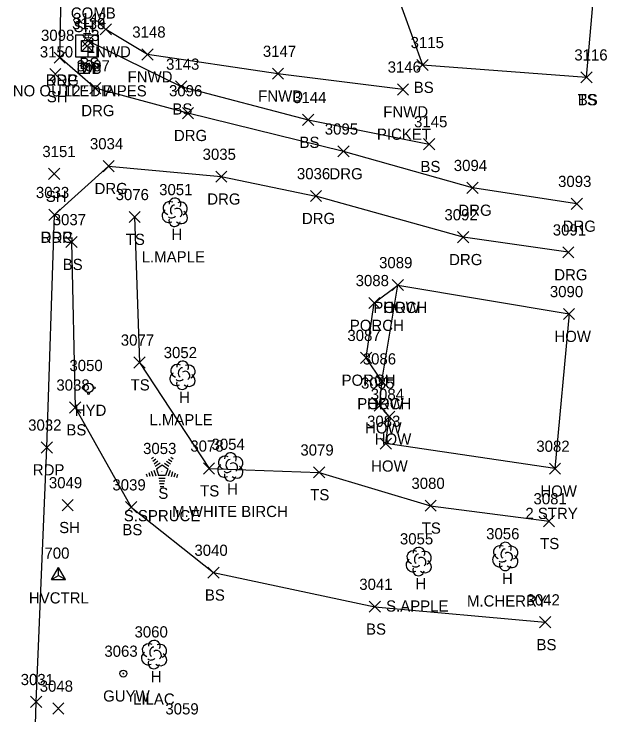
# Model space of a CAD drawing. Extents: x 1609623 to 1616187, y 756677 to 762826.
# Drawn here: x 1610619.9 to 1610725.9, y 762230.4 to 762355.6 of the extents above; entities that cross this region are included whole.
import ezdxf

# ---------------------------------------------------------------- set-up
doc = ezdxf.new("R2010")
doc.units = 0
for name, color, linetype in [('C_A', 7, 'Continuous'), ('C_I', 7, 'Continuous'), ('CPSM', 7, 'Continuous'), ('D_A', 7, 'Continuous'), ('D_C', 7, 'Continuous'), ('D_I', 7, 'Continuous'), ('D_TIC', 7, 'Continuous'), ('DS', 7, 'Continuous'), ('L_A', 7, 'Continuous'), ('L_C', 7, 'Continuous'), ('L_I', 7, 'Continuous'), ('L_TIC', 7, 'Continuous'), ('LBC', 7, 'Continuous'), ('LBF', 7, 'Continuous'), ('LELB', 7, 'Continuous'), ('LFNC', 7, 'Continuous'), ('LTC', 7, 'Continuous'), ('LTD', 7, 'Continuous'), ('P_A', 7, 'Continuous'), ('P_I', 7, 'Continuous'), ('P_TIC', 7, 'Continuous'), ('PET', 7, 'Continuous'), ('R_A', 7, 'Continuous'), ('R_I', 7, 'Continuous'), ('R_TIC', 7, 'Continuous'), ('RDG', 7, 'Continuous'), ('U_A', 7, 'Continuous'), ('U_C', 7, 'Continuous'), ('U_I', 7, 'Continuous'), ('UPGW', 7, 'Continuous'), ('UWFH', 7, 'Continuous')]:
    doc.layers.add(name, color=color, linetype=linetype)

msp = doc.modelspace()

# ---------------------------------------------------------------- linework, layer by layer
at = {"layer": 'CPSM'}
for p, q in [((1610626.64, 762254.57), (1610627.89, 762256.74)), ((1610629.14, 762254.57), (1610627.89, 762256.74)), ((1610627.89, 762255.3), (1610627.89, 762256.74)), ((1610626.64, 762254.57), (1610627.89, 762255.3)), ((1610627.89, 762255.3), (1610627.89, 762255.3)), ((1610627.89, 762255.3), (1610629.14, 762254.57)), ((1610626.64, 762254.57), (1610629.14, 762254.57))]:
    msp.add_line(p, q, dxfattribs=at)
at = {"layer": 'D_TIC'}
for points in [[(1610631.99, 762348.87), (1610633.99, 762350.87)], [(1610633.99, 762348.87), (1610631.99, 762350.87)]]:
    msp.add_lwpolyline(points, dxfattribs=at)
at = {"layer": 'DS'}
for p, q in [((1610630.97, 762351.87), (1610634.97, 762351.87)), ((1610630.97, 762347.87), (1610630.97, 762351.87)), ((1610634.97, 762351.87), (1610634.97, 762347.87)), ((1610631.97, 762348.87), (1610631.97, 762350.87)), ((1610631.97, 762350.87), (1610633.97, 762350.87)), ((1610633.97, 762350.87), (1610633.97, 762348.87)), ((1610632.98, 762349.87), (1610632.98, 762349.87)), ((1610632.98, 762349.87), (1610632.98, 762349.87)), ((1610634.97, 762347.87), (1610630.97, 762347.87)), ((1610633.97, 762348.87), (1610631.97, 762348.87))]:
    msp.add_line(p, q, dxfattribs=at)
at = {"layer": 'L_TIC'}
for points in [[(1610635.31, 762351.84), (1610637.31, 762353.84)], [(1610637.31, 762351.84), (1610635.31, 762353.84)], [(1610632.16, 762349.79), (1610634.16, 762351.79)], [(1610634.16, 762349.79), (1610632.16, 762351.79)], [(1610642.75, 762347.37), (1610644.75, 762349.37)], [(1610644.75, 762347.37), (1610642.75, 762349.37)], [(1610691.89, 762345.49), (1610693.89, 762347.49)], [(1610693.89, 762345.49), (1610691.89, 762347.49)], [(1610626.31, 762343.83), (1610628.31, 762345.83)], [(1610628.31, 762343.83), (1610626.31, 762345.83)], [(1610666.07, 762343.93), (1610668.07, 762345.93)], [(1610668.07, 762343.93), (1610666.07, 762345.93)], [(1610721.2, 762343.28), (1610723.2, 762345.28)], [(1610723.2, 762343.28), (1610721.2, 762345.28)], [(1610721.2, 762343.28), (1610723.2, 762345.28)], [(1610723.2, 762343.28), (1610721.2, 762345.28)], [(1610648.78, 762341.63), (1610650.78, 762343.63)], [(1610650.78, 762341.63), (1610648.78, 762343.63)], [(1610688.42, 762341.12), (1610690.42, 762343.12)], [(1610690.42, 762341.12), (1610688.42, 762343.12)], [(1610671.47, 762335.67), (1610673.47, 762337.67)], [(1610673.47, 762335.67), (1610671.47, 762337.67)], [(1610693.09, 762331.35), (1610695.09, 762333.35)], [(1610695.09, 762331.35), (1610693.09, 762333.35)], [(1610626.1, 762326.03), (1610628.1, 762328.03)], [(1610628.1, 762326.03), (1610626.1, 762328.03)], [(1610640.47, 762318.34), (1610642.47, 762320.34)], [(1610642.47, 762318.34), (1610640.47, 762320.34)], [(1610629.18, 762313.86), (1610631.18, 762315.86)], [(1610631.18, 762313.86), (1610629.18, 762315.86)], [(1610687.49, 762306.18), (1610689.49, 762308.18)], [(1610689.49, 762306.18), (1610687.49, 762308.18)], [(1610687.49, 762306.18), (1610689.49, 762308.18)], [(1610689.49, 762306.18), (1610687.49, 762308.18)], [(1610683.29, 762302.98), (1610685.29, 762304.98)], [(1610685.29, 762302.98), (1610683.29, 762304.98)], [(1610718.07, 762301.01), (1610720.07, 762303.01)], [(1610720.07, 762301.01), (1610718.07, 762303.01)], [(1610681.82, 762293.18), (1610683.82, 762295.18)], [(1610683.82, 762293.18), (1610681.82, 762295.18)], [(1610641.34, 762292.35), (1610643.34, 762294.35)], [(1610643.34, 762292.35), (1610641.34, 762294.35)], [(1610684.62, 762288.99), (1610686.62, 762290.99)], [(1610686.62, 762288.99), (1610684.62, 762290.99)], [(1610684.62, 762288.99), (1610686.62, 762290.99)], [(1610686.62, 762288.99), (1610684.62, 762290.99)], [(1610684.25, 762284.67), (1610686.25, 762286.67)], [(1610686.25, 762284.67), (1610684.25, 762286.67)], [(1610629.83, 762284.32), (1610631.83, 762286.32)], [(1610631.83, 762284.32), (1610629.83, 762286.32)], [(1610685.97, 762282.67), (1610687.97, 762284.67)], [(1610687.97, 762282.67), (1610685.97, 762284.67)], [(1610685.34, 762277.85), (1610687.34, 762279.85)], [(1610687.34, 762277.85), (1610685.34, 762279.85)], [(1610653.76, 762273.42), (1610655.76, 762275.42)], [(1610655.76, 762273.42), (1610653.76, 762275.42)], [(1610715.56, 762273.39), (1610717.56, 762275.39)], [(1610717.56, 762273.39), (1610715.56, 762275.39)], [(1610673.42, 762272.72), (1610675.42, 762274.72)], [(1610675.42, 762272.72), (1610673.42, 762274.72)], [(1610628.5, 762266.87), (1610630.5, 762268.87)], [(1610630.5, 762266.87), (1610628.5, 762268.87)], [(1610639.84, 762266.49), (1610641.84, 762268.49)], [(1610641.84, 762266.49), (1610639.84, 762268.49)], [(1610693.35, 762266.77), (1610695.35, 762268.77)], [(1610695.35, 762266.77), (1610693.35, 762268.77)], [(1610714.5, 762264.01), (1610716.5, 762266.01)], [(1610716.5, 762264.01), (1610714.5, 762266.01)], [(1610654.57, 762254.81), (1610656.57, 762256.81)], [(1610656.57, 762254.81), (1610654.57, 762256.81)], [(1610683.37, 762248.73), (1610685.37, 762250.73)], [(1610685.37, 762248.73), (1610683.37, 762250.73)], [(1610713.81, 762245.95), (1610715.81, 762247.95)], [(1610715.81, 762245.95), (1610713.81, 762247.95)], [(1610626.84, 762230.54), (1610628.84, 762232.54)], [(1610628.84, 762230.54), (1610626.84, 762232.54)]]:
    msp.add_lwpolyline(points, dxfattribs=at)
at = {"layer": 'LBC'}
for points in [[(1610716.56, 762274.39), (1610686.34, 762278.85), (1610686.97, 762283.67), (1610685.25, 762285.67), (1610685.62, 762289.99), (1610688.49, 762307.18), (1610719.07, 762302.01)], [(1610719.07, 762302.01), (1610716.56, 762274.39)]]:
    msp.add_lwpolyline(points, dxfattribs=at)
at = {"layer": 'LBF'}
msp.add_lwpolyline([(1610685.62, 762289.99), (1610682.82, 762294.18), (1610684.29, 762303.98), (1610688.49, 762307.18)], dxfattribs=at)
at = {"layer": 'LELB'}
for points in [[(1610697.13, 762426.27), (1610674.89, 762430.11), (1610652.17, 762434), (1610639.18, 762426.74), (1610634.28, 762401.02), (1610634.83, 762377.24), (1610647.78, 762368.68), (1610668.95, 762368.97), (1610685.96, 762365.63), (1610692.89, 762346.49), (1610722.2, 762344.28)], [(1610722.2, 762344.28), (1610724.11, 762366.05), (1610703.11, 762368.06), (1610688.81, 762373.62), (1610671.14, 762377.72), (1610655.71, 762382.19), (1610654.46, 762391.1), (1610655.72, 762413.08), (1610653.02, 762429.54), (1610669.88, 762427.1), (1610693.44, 762424.02)], [(1610633.16, 762350.79), (1610649.78, 762342.63), (1610672.47, 762336.67), (1610694.09, 762332.35)], [(1610641.47, 762319.34), (1610642.34, 762293.35), (1610654.76, 762274.42), (1610674.42, 762273.72), (1610694.35, 762267.77), (1610715.5, 762265.01)], [(1610630.18, 762314.86), (1610630.83, 762285.32), (1610640.84, 762267.49), (1610655.57, 762255.81), (1610684.37, 762249.73), (1610714.81, 762246.95)]]:
    msp.add_lwpolyline(points, dxfattribs=at)
at = {"layer": 'LFNC'}
msp.add_lwpolyline([(1610689.42, 762342.12), (1610667.07, 762344.93), (1610643.75, 762348.37), (1610636.31, 762352.84)], dxfattribs=at)
at = {"layer": 'LTC'}
for p, q in [((1610644.51, 762276.19), (1610644.86, 762276.45)), ((1610647.91, 762276.43), (1610648.33, 762276.13)), ((1610644.72, 762275.73), (1610645.25, 762276.11)), ((1610644.93, 762275.26), (1610645.63, 762275.77)), ((1610645.14, 762274.8), (1610646.02, 762275.43)), ((1610645.36, 762274.34), (1610646.37, 762275.08)), ((1610646.37, 762275.08), (1610647.37, 762274.35)), ((1610646.79, 762275.39), (1610647.6, 762274.8)), ((1610647.17, 762275.74), (1610647.85, 762275.24)), ((1610647.54, 762276.09), (1610648.09, 762275.69)), ((1610644.45, 762273.91), (1610644.72, 762273.07)), ((1610644.91, 762274.12), (1610645.24, 762273.1)), ((1610645.36, 762274.34), (1610645.75, 762273.15)), ((1610647.37, 762274.35), (1610646.98, 762273.15)), ((1610647.81, 762274.08), (1610647.47, 762273.04)), ((1610648.25, 762273.83), (1610647.97, 762272.95)), ((1610643.54, 762273.47), (1610643.69, 762273)), ((1610644, 762273.69), (1610644.21, 762273.04)), ((1610646.98, 762273.15), (1610645.75, 762273.15)), ((1610646.94, 762272.65), (1610645.8, 762272.65)), ((1610648.7, 762273.58), (1610648.46, 762272.85)), ((1610649.14, 762273.33), (1610648.96, 762272.76)), ((1610646.86, 762272.15), (1610645.87, 762272.15)), ((1610646.77, 762271.65), (1610645.94, 762271.65)), ((1610646.69, 762271.15), (1610646.02, 762271.15))]:
    msp.add_line(p, q, dxfattribs=at)
at = {"layer": 'LTD'}
for p, q in [((1610648.62, 762320.22), (1610648.62, 762320.22)), ((1610648.62, 762320.22), (1610648.62, 762320.22)), ((1610650, 762291.12), (1610650, 762291.12)), ((1610650, 762291.12), (1610650, 762291.12)), ((1610658.54, 762274.74), (1610658.54, 762274.74)), ((1610658.54, 762274.74), (1610658.54, 762274.74)), ((1610692.2, 762257.85), (1610692.2, 762257.85)), ((1610692.2, 762257.85), (1610692.2, 762257.85)), ((1610707.66, 762258.76), (1610707.66, 762258.76)), ((1610707.66, 762258.76), (1610707.66, 762258.76)), ((1610644.92, 762241.23), (1610644.92, 762241.23)), ((1610644.92, 762241.23), (1610644.92, 762241.23))]:
    msp.add_line(p, q, dxfattribs=at)
for centre in [(1610648.66, 762321.65), (1610650.04, 762292.55), (1610658.59, 762276.18), (1610692.25, 762259.28), (1610707.71, 762260.19), (1610644.97, 762242.67)]:
    msp.add_arc(centre, 1.05, 335.5272, 180.9563, dxfattribs=at)
for centre, major_axis, ratio, start_param, end_param in [((1610647.83, 762320.88), (1.21, -0.51), 0.895232, 1.570796, 4.712389), ((1610648.41, 762320.67), (-0.208, -0.792), 0.645439, 3.141593, 6.283185), ((1610649.66, 762320.8), (-1.14, -0.48), 0.949671, 1.570796, 4.712389), ((1610647.53, 762319.51), (0.58, -1.04), 0.959034, 3.141593, 6.283185), ((1610649.12, 762320.05), (-0.5, 0.667), 0.989748, 3.141593, 6.283185), ((1610649.62, 762319.38), (-1.09, 0.79), 0.841452, 1.570796, 4.712389), ((1610648.62, 762318.72), (0.26, 1.06), 0.942809, 1.570796, 4.712389), ((1610648.16, 762319.47), (-0.625, -0.083), 0.423636, 0, 3.141593), ((1610649.21, 762291.79), (1.21, -0.51), 0.895232, 1.570796, 4.712389), ((1610651.04, 762291.7), (-1.14, -0.48), 0.949671, 1.570796, 4.712389), ((1610648.91, 762290.41), (0.58, -1.04), 0.959034, 3.141593, 6.283185), ((1610649.79, 762291.58), (-0.208, -0.792), 0.645439, 3.141593, 6.283185), ((1610650.5, 762290.95), (-0.5, 0.667), 0.989748, 3.141593, 6.283185), ((1610649.54, 762290.37), (-0.625, -0.083), 0.423636, 0, 3.141593), ((1610651, 762290.29), (-1.09, 0.79), 0.841452, 1.570796, 4.712389), ((1610650, 762289.62), (0.26, 1.06), 0.942809, 1.570796, 4.712389), ((1610657.75, 762275.41), (1.21, -0.51), 0.895232, 1.570796, 4.712389), ((1610659.58, 762275.33), (-1.14, -0.48), 0.949671, 1.570796, 4.712389), ((1610657.46, 762274.04), (0.58, -1.04), 0.959034, 3.141593, 6.283185), ((1610658.33, 762275.2), (-0.208, -0.792), 0.645439, 3.141593, 6.283185), ((1610659.04, 762274.58), (-0.5, 0.667), 0.989748, 3.141593, 6.283185), ((1610658.08, 762273.99), (-0.625, -0.083), 0.423636, 0, 3.141593), ((1610659.54, 762273.91), (-1.09, 0.79), 0.841452, 1.570796, 4.712389), ((1610658.54, 762273.24), (0.26, 1.06), 0.942809, 1.570796, 4.712389), ((1610706.87, 762259.43), (1.21, -0.51), 0.895232, 1.570796, 4.712389), ((1610707.45, 762259.22), (-0.208, -0.792), 0.645439, 3.141593, 6.283185), ((1610708.7, 762259.34), (-1.14, -0.48), 0.949671, 1.570796, 4.712389), ((1610691.41, 762258.51), (1.21, -0.51), 0.895232, 1.570796, 4.712389), ((1610691.99, 762258.31), (-0.208, -0.792), 0.645439, 3.141593, 6.283185), ((1610693.24, 762258.43), (-1.14, -0.48), 0.949671, 1.570796, 4.712389), ((1610706.58, 762258.05), (0.58, -1.04), 0.959034, 3.141593, 6.283185), ((1610708.16, 762258.59), (-0.5, 0.667), 0.989748, 3.141593, 6.283185), ((1610708.66, 762257.93), (-1.09, 0.79), 0.841452, 1.570796, 4.712389), ((1610691.12, 762257.14), (0.58, -1.04), 0.959034, 3.141593, 6.283185), ((1610692.7, 762257.68), (-0.5, 0.667), 0.989748, 3.141593, 6.283185), ((1610693.2, 762257.01), (-1.09, 0.79), 0.841452, 1.570796, 4.712389), ((1610707.2, 762258.01), (-0.625, -0.083), 0.423636, 0, 3.141593), ((1610692.2, 762256.35), (0.26, 1.06), 0.942809, 1.570796, 4.712389), ((1610691.74, 762257.1), (-0.625, -0.083), 0.423636, 0, 3.141593), ((1610707.66, 762257.26), (0.26, 1.06), 0.942809, 1.570796, 4.712389), ((1610644.13, 762241.9), (1.21, -0.51), 0.895232, 1.570796, 4.712389), ((1610644.71, 762241.69), (-0.208, -0.792), 0.645439, 3.141593, 6.283185), ((1610645.96, 762241.82), (-1.14, -0.48), 0.949671, 1.570796, 4.712389), ((1610643.84, 762240.53), (0.58, -1.04), 0.959034, 3.141593, 6.283185), ((1610645.42, 762241.07), (-0.5, 0.667), 0.989748, 3.141593, 6.283185), ((1610645.92, 762240.4), (-1.09, 0.79), 0.841452, 1.570796, 4.712389), ((1610644.46, 762240.48), (-0.625, -0.083), 0.423636, 0, 3.141593), ((1610644.92, 762239.73), (0.26, 1.06), 0.942809, 1.570796, 4.712389)]:
    msp.add_ellipse(centre, major_axis=major_axis, ratio=ratio, start_param=start_param, end_param=end_param, dxfattribs=at)
at = {"layer": 'P_TIC'}
for points in [[(1610627.08, 762346.79), (1610629.08, 762348.79)], [(1610629.08, 762346.79), (1610627.08, 762348.79)], [(1610626.17, 762318.71), (1610628.17, 762320.71)], [(1610628.17, 762318.71), (1610626.17, 762320.71)], [(1610624.79, 762277.17), (1610626.79, 762279.17)], [(1610626.79, 762277.17), (1610624.79, 762279.17)], [(1610622.89, 762231.72), (1610624.89, 762233.72)], [(1610624.89, 762231.72), (1610622.89, 762233.72)]]:
    msp.add_lwpolyline(points, dxfattribs=at)
at = {"layer": 'PET'}
for points in [[(1610628.08, 762347.79), (1610628.95, 762388.2), (1610629.07, 762418.54), (1610628.85, 762445.72)], [(1610622.57, 762187.86), (1610623.89, 762232.72), (1610625.79, 762278.17), (1610627.17, 762319.71)]]:
    msp.add_lwpolyline(points, dxfattribs=at)
at = {"layer": 'R_TIC'}
for points in [[(1610627.08, 762346.79), (1610629.08, 762348.79)], [(1610629.08, 762346.79), (1610627.08, 762348.79)], [(1610633.44, 762341.34), (1610635.44, 762343.34)], [(1610635.44, 762341.34), (1610633.44, 762343.34)], [(1610650, 762336.89), (1610652, 762338.89)], [(1610652, 762336.89), (1610650, 762338.89)], [(1610677.78, 762330.05), (1610679.78, 762332.05)], [(1610679.78, 762330.05), (1610677.78, 762332.05)], [(1610635.82, 762327.42), (1610637.82, 762329.42)], [(1610637.82, 762327.42), (1610635.82, 762329.42)], [(1610655.95, 762325.54), (1610657.95, 762327.54)], [(1610657.95, 762325.54), (1610655.95, 762327.54)], [(1610700.82, 762323.54), (1610702.82, 762325.54)], [(1610702.82, 762323.54), (1610700.82, 762325.54)], [(1610672.86, 762322.07), (1610674.86, 762324.07)], [(1610674.86, 762322.07), (1610672.86, 762324.07)], [(1610719.46, 762320.69), (1610721.46, 762322.69)], [(1610721.46, 762320.69), (1610719.46, 762322.69)], [(1610626.17, 762318.71), (1610628.17, 762320.71)], [(1610628.17, 762318.71), (1610626.17, 762320.71)], [(1610699.16, 762314.73), (1610701.16, 762316.73)], [(1610701.16, 762314.73), (1610699.16, 762316.73)], [(1610717.94, 762312.02), (1610719.94, 762314.02)], [(1610719.94, 762312.02), (1610717.94, 762314.02)]]:
    msp.add_lwpolyline(points, dxfattribs=at)
at = {"layer": 'RDG'}
for points in [[(1610720.46, 762321.69), (1610701.82, 762324.54), (1610678.78, 762331.05), (1610651, 762337.89), (1610634.44, 762342.34), (1610628.08, 762347.79)], [(1610627.17, 762319.71), (1610636.82, 762328.42), (1610656.95, 762326.54), (1610673.86, 762323.07)], [(1610700.16, 762315.73), (1610673.86, 762323.07)], [(1610718.94, 762313.02), (1610700.16, 762315.73)]]:
    msp.add_lwpolyline(points, dxfattribs=at)
at = {"layer": 'UPGW'}
for radius in [0.625, 0.0833]:
    msp.add_circle((1610639.45, 762237.78), radius, dxfattribs=at)
at = {"layer": 'UWFH'}
msp.add_line((1610633.25, 762288.81), (1610633.25, 762288.81), dxfattribs=at)
for centre, radius in [((1610632.25, 762288.81), 0.167), ((1610633.25, 762288.81), 0.833), ((1610634.25, 762288.81), 0.167), ((1610633.25, 762287.81), 0.167)]:
    msp.add_circle(centre, radius, dxfattribs=at)

# ---------------------------------------------------------------- texts
at = {"layer": 'C_A'}
msp.add_text('HVCTRL', height=2, dxfattribs=at).set_placement((1610622.58, 762250.3))
at = {"layer": 'C_I'}
msp.add_text('700', height=2, dxfattribs=at).set_placement((1610625.36, 762258.3))
at = {"layer": 'D_A'}
for s, p in [('DIB', (1610631.09, 762344.87)), ('DI', (1610632.03, 762344.87))]:
    msp.add_text(s, height=2, dxfattribs=at).set_placement(p)
at = {"layer": 'D_C'}
for s, p in [('NO OUTLET PIPES', (1610619.7, 762340.87)), ('12" DIA', (1610628.84, 762340.87))]:
    msp.add_text(s, height=2, dxfattribs=at).set_placement(p)
at = {"layer": 'D_I'}
for s in ['3138', '3139']:
    msp.add_text(s, height=2, dxfattribs=at).set_placement((1610630.29, 762352.87))
at = {"layer": 'L_A'}
for s, p in [('SH', (1610630.57, 762352.35)), ('FNWD', (1610632.77, 762347.84)), ('BS', (1610631.61, 762345.79)), ('FNWD', (1610640.21, 762343.37)), ('BS', (1610691.33, 762341.49)), ('SH', (1610625.79, 762339.83)), ('FNWD', (1610663.54, 762339.93)), ('TS', (1610720.61, 762339.28)), ('BS', (1610720.64, 762339.28)), ('BS', (1610648.22, 762337.63)), ('FNWD', (1610685.88, 762337.12)), ('BS', (1610670.92, 762331.67)), ('BS', (1610692.53, 762327.35)), ('SH', (1610625.59, 762322.03)), ('H', (1610648.05, 762315.22)), ('TS', (1610639.88, 762314.34)), ('BS', (1610628.62, 762309.86)), ('PORCH', (1610684.11, 762302.18)), ('HOW', (1610685.88, 762302.18)), ('PORCH', (1610679.91, 762298.98)), ('HOW', (1610716.46, 762297.01)), ('TS', (1610640.75, 762288.35)), ('PORCH', (1610678.44, 762289.18)), ('H', (1610649.43, 762286.12)), ('PORCH', (1610681.24, 762284.99)), ('HOW', (1610683.01, 762284.99)), ('HOW', (1610682.63, 762280.67)), ('BS', (1610629.27, 762280.32)), ('HOW', (1610684.36, 762278.67)), ('HOW', (1610683.72, 762273.85)), ('TS', (1610653.17, 762269.42)), ('H', (1610657.97, 762269.74)), ('HOW', (1610713.95, 762269.39)), ('S', (1610645.7, 762268.99)), ('TS', (1610672.83, 762268.72)), ('SH', (1610627.99, 762262.87)), ('BS', (1610639.28, 762262.49)), ('TS', (1610692.76, 762262.77)), ('TS', (1610713.91, 762260.01)), ('H', (1610707.09, 762253.76)), ('H', (1610691.63, 762252.85)), ('BS', (1610654.02, 762250.81)), ('BS', (1610682.81, 762244.73)), ('BS', (1610713.26, 762241.95)), ('H', (1610644.35, 762236.23))]:
    msp.add_text(s, height=2, dxfattribs=at).set_placement(p)
at = {"layer": 'L_C'}
for s, p in [('PICKET', (1610684.75, 762333.12)), ('L.MAPLE', (1610642.73, 762311.22)), ('L.MAPLE', (1610644.11, 762282.12)), ('M.WHITE BIRCH', (1610648.18, 762265.74)), ('S.SPRUCE', (1610639.53, 762264.99)), ('2 STRY', (1610711.27, 762265.39)), ('M.CHERRY', (1610700.84, 762249.76)), ('S.APPLE', (1610686.39, 762248.85)), ('LILAC', (1610641.19, 762232.23))]:
    msp.add_text(s, height=2, dxfattribs=at).set_placement(p)
at = {"layer": 'L_I'}
for s, p in [('3142', (1610630.47, 762353.79)), ('3148', (1610641.05, 762351.37)), ('3115', (1610690.77, 762349.49)), ('3150', (1610624.53, 762347.83)), ('3147', (1610664.38, 762347.93)), ('3116', (1610720.02, 762347.28)), ('3116', (1610720.02, 762347.28)), ('3143', (1610647.08, 762345.63)), ('3146', (1610686.67, 762345.12)), ('3144', (1610669.78, 762339.67)), ('3145', (1610691.39, 762335.35)), ('3151', (1610624.98, 762330.03)), ('3051', (1610645.85, 762323.22)), ('3076', (1610638.07, 762322.34)), ('3037', (1610626.84, 762317.86)), ('3089', (1610685.14, 762310.18)), ('3089', (1610685.14, 762310.18)), ('3088', (1610680.95, 762306.98)), ('3090', (1610715.65, 762305.01)), ('3087', (1610679.48, 762297.18)), ('3077', (1610639, 762296.35)), ('3052', (1610646.66, 762294.12)), ('3086', (1610682.23, 762292.99)), ('3086', (1610682.23, 762292.99)), ('3038', (1610627.49, 762288.32)), ('3085', (1610681.91, 762288.67)), ('3084', (1610683.64, 762286.67)), ('3083', (1610683, 762281.85)), ('3053', (1610642.98, 762276.99)), ('3078', (1610651.42, 762277.42)), ('3054', (1610655.2, 762277.74)), ('3082', (1610713.23, 762277.39)), ('3079', (1610671.08, 762276.72)), ('3049', (1610626.15, 762270.87)), ('3080', (1610690.92, 762270.77)), ('3039', (1610637.5, 762270.49)), ('3081', (1610712.73, 762268.01)), ('3055', (1610688.86, 762260.85)), ('3056', (1610704.27, 762261.76)), ('3040', (1610652.15, 762258.81)), ('3041', (1610681.6, 762252.73)), ('3042', (1610711.48, 762249.95)), ('3060', (1610641.45, 762244.23)), ('3048', (1610624.51, 762234.54)), ('3059', (1610646.96, 762230.48))]:
    msp.add_text(s, height=2, dxfattribs=at).set_placement(p)
at = {"layer": 'LTC'}
msp.add_text('.', height=1.04, rotation=270, dxfattribs=at).set_placement((1610646.26, 762274.09))
at = {"layer": 'P_A'}
for p in [(1610625.57, 762342.79), (1610624.66, 762314.71), (1610623.28, 762273.17)]:
    msp.add_text('RDP', height=2, dxfattribs=at).set_placement(p)
at = {"layer": 'P_I'}
for s, p in [('3098', (1610624.74, 762350.79)), ('3033', (1610623.83, 762322.71)), ('3032', (1610622.45, 762281.17)), ('3031', (1610621.11, 762235.72))]:
    msp.add_text(s, height=2, dxfattribs=at).set_placement(p)
at = {"layer": 'R_A'}
for p in [(1610625.57, 762342.79), (1610631.93, 762337.34), (1610648.49, 762332.89), (1610676.27, 762326.05), (1610634.31, 762323.42), (1610654.44, 762321.54), (1610699.31, 762319.54), (1610671.35, 762318.07), (1610717.94, 762316.69), (1610624.66, 762314.71), (1610697.65, 762310.73), (1610716.43, 762308.02)]:
    msp.add_text('DRG', height=2, dxfattribs=at).set_placement(p)
at = {"layer": 'R_I'}
for s, p in [('3098', (1610624.74, 762350.79)), ('3097', (1610631.1, 762345.34)), ('3096', (1610647.61, 762340.89)), ('3095', (1610675.44, 762334.05)), ('3034', (1610633.48, 762331.42)), ('3035', (1610653.61, 762329.54)), ('3094', (1610698.49, 762327.54)), ('3036', (1610670.46, 762326.07)), ('3093', (1610717.12, 762324.69)), ('3033', (1610623.83, 762322.71)), ('3092', (1610696.82, 762318.73)), ('3091', (1610716.17, 762316.02))]:
    msp.add_text(s, height=2, dxfattribs=at).set_placement(p)
at = {"layer": 'U_A'}
for s, p in [('COMB', (1610630.07, 762354.76)), ('HYD', (1610630.77, 762283.81)), ('GUYW', (1610635.84, 762232.78))]:
    msp.add_text(s, height=2, dxfattribs=at).set_placement(p)
at = {"layer": 'U_C'}
msp.add_text('#3', height=2, dxfattribs=at).set_placement((1610632.22, 762350.76))
at = {"layer": 'U_I'}
for s, p in [('3050', (1610629.82, 762291.81)), ('3063', (1610636.06, 762240.78))]:
    msp.add_text(s, height=2, dxfattribs=at).set_placement(p)

doc.saveas('drawing.dxf')
